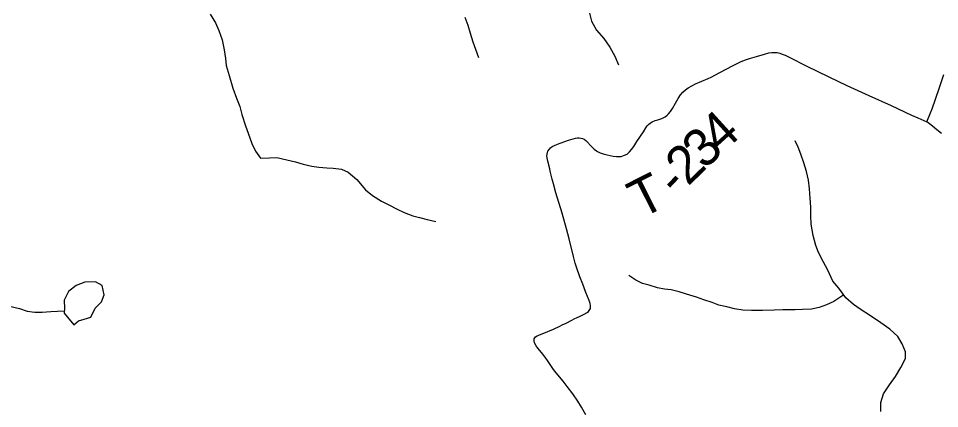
# Model space of a CAD drawing. Extents: x 0 to 34, y 0 to 22.
# Drawn here: x 5.89 to 7.268, y 16.898 to 17.482 of the extents above; entities that cross this region are included whole.
import ezdxf

# ---------------------------------------------------------------- set-up
doc = ezdxf.new("R2010")
doc.units = 0
for name, color, linetype in [('GM_X_Minor_Lake', 7, 'Continuous'), ('GM_X_Minor_River', 7, 'Continuous'), ('GM_X_Township_Road', 7, 'Continuous'), ('GM_X_Township_Road_Text', 7, 'Continuous')]:
    doc.layers.add(name, color=color, linetype=linetype)

msp = doc.modelspace()

# ---------------------------------------------------------------- linework, layer by layer
at = {"layer": 'GM_X_Minor_Lake'}
for points in [[(5.9725, 17.0228), (5.9798, 17.0291), (5.9882, 17.0317), (5.9981, 17.0346), (6.0044, 17.0478), (6.014, 17.0575), (6.0179, 17.0681), (6.0151, 17.0818), (6.0049, 17.0873), (5.989, 17.0871), (5.9764, 17.082), (5.9649, 17.073), (5.9583, 17.0598), (5.9585, 17.0477), (5.9584, 17.0404)], [(5.9584, 17.0404), (5.9725, 17.0228)]]:
    msp.add_lwpolyline(points, dxfattribs=at)
at = {"layer": 'GM_X_Minor_River'}
for points in [[(6.1768, 17.4886), (6.1846, 17.4756), (6.1897, 17.4637), (6.1949, 17.45), (6.1977, 17.4351), (6.1998, 17.4218), (6.2007, 17.4115), (6.2051, 17.3966), (6.2105, 17.3775), (6.216, 17.3627), (6.2211, 17.35), (6.2243, 17.3382), (6.2298, 17.321), (6.2334, 17.31), (6.2389, 17.2947), (6.2448, 17.2832), (6.2522, 17.2725), (6.2655, 17.2734), (6.2765, 17.2736), (6.2916, 17.2704), (6.3044, 17.2671), (6.3158, 17.2636), (6.329, 17.2607), (6.3392, 17.259), (6.3513, 17.2581), (6.3608, 17.2576), (6.3733, 17.2562), (6.3835, 17.2515), (6.3962, 17.2407), (6.4092, 17.2253), (6.4197, 17.2168), (6.4333, 17.2083), (6.4442, 17.2028), (6.4566, 17.1965), (6.4671, 17.1914), (6.4799, 17.1863), (6.4902, 17.1839), (6.5015, 17.1807), (6.5147, 17.1778)], [(6.5578, 17.4841), (6.5622, 17.4719), (6.5658, 17.4601), (6.5698, 17.4471), (6.5738, 17.436), (6.5786, 17.4234)], [(6.7445, 17.4897), (6.7477, 17.4779), (6.7551, 17.4645), (6.7659, 17.4518), (6.7748, 17.4391), (6.7826, 17.4253), (6.7881, 17.4123)], [(7.2026, 16.9457), (7.2107, 16.9589), (7.2177, 16.9725), (7.2175, 16.9823), (7.2127, 16.9946), (7.2061, 17.0053), (7.1941, 17.0165), (7.1806, 17.0262), (7.1652, 17.0363), (7.1494, 17.0464), (7.1397, 17.0534), (7.1284, 17.0634), (7.1177, 17.078), (7.1087, 17.0884), (7.101, 17.1049), (7.0943, 17.1179), (7.0873, 17.1313), (7.0833, 17.1416), (7.0794, 17.1569), (7.0762, 17.174), (7.076, 17.1869), (7.0758, 17.1995), (7.0749, 17.2128), (7.0739, 17.2268), (7.0722, 17.2398), (7.0694, 17.2527), (7.0654, 17.2657), (7.0607, 17.2787), (7.0566, 17.289), (7.0522, 17.2986)], [(7.125, 17.0681), (7.1102, 17.058), (7.0991, 17.0529), (7.0884, 17.0492), (7.0766, 17.0467), (7.0633, 17.0458), (7.0523, 17.0456), (7.0338, 17.0455), (7.0209, 17.0449), (7.0034, 17.0444), (6.9871, 17.0443), (6.9738, 17.0448), (6.9614, 17.0469), (6.95, 17.0498), (6.9379, 17.0522), (6.9281, 17.0562), (6.9157, 17.0605), (6.9047, 17.0645), (6.8896, 17.0689), (6.8787, 17.0725), (6.8666, 17.0753), (6.8568, 17.0766), (6.8462, 17.0783), (6.8337, 17.0823), (6.8239, 17.0851), (6.8141, 17.0898), (6.8036, 17.0968)], [(5.8762, 17.0508), (5.8914, 17.0475), (5.9027, 17.0435), (5.9144, 17.0422), (5.9254, 17.0421), (5.9383, 17.043), (5.9584, 17.0439)], [(7.1806, 16.8929), (7.1808, 16.9065), (7.1847, 16.9194), (7.1937, 16.9333), (7.2026, 16.9457)]]:
    msp.add_lwpolyline(points, dxfattribs=at)
at = {"layer": 'GM_X_Township_Road'}
for points in [[(6.6822, 17.2834), (6.6844, 17.2864), (6.6862, 17.2881), (6.6887, 17.2899), (6.692, 17.2917), (6.6965, 17.2937), (6.7129, 17.2994), (6.7237, 17.3025), (6.7267, 17.3029), (6.7292, 17.303), (6.7317, 17.3027), (6.734, 17.302), (6.7363, 17.3009), (6.7389, 17.2992), (6.7412, 17.2972), (6.7467, 17.2913), (6.7515, 17.2864), (6.7549, 17.2837), (6.7565, 17.2827), (6.7603, 17.2807), (6.765, 17.2791), (6.771, 17.2775), (6.7801, 17.2756), (6.7851, 17.275), (6.79, 17.2752), (6.7918, 17.2754), (6.7971, 17.277), (6.801, 17.2789), (6.8046, 17.2823), (6.8074, 17.2857), (6.8107, 17.2902), (6.8155, 17.2974), (6.8251, 17.3119), (6.8289, 17.3183), (6.8307, 17.3209), (6.8328, 17.3231), (6.8356, 17.3255), (6.8382, 17.3271), (6.8427, 17.3291), (6.8469, 17.3301), (6.8528, 17.3321), (6.8577, 17.3347), (6.8606, 17.337), (6.8628, 17.3391), (6.8657, 17.3424), (6.8689, 17.347), (6.8733, 17.3552), (6.8771, 17.3623), (6.8805, 17.3674), (6.8842, 17.3716), (6.8883, 17.3752), (6.8924, 17.378), (6.8977, 17.3812), (6.9033, 17.3839), (6.9124, 17.3878), (6.9221, 17.392), (6.9266, 17.3941), (6.9397, 17.401), (6.9594, 17.4115), (6.9716, 17.4175), (6.9779, 17.4201), (6.9838, 17.422), (6.9945, 17.4251), (7.0064, 17.4287), (7.013, 17.4304), (7.0173, 17.431), (7.0203, 17.4312), (7.0253, 17.4309), (7.0295, 17.4299), (7.033, 17.4287), (7.0376, 17.4268), (7.0454, 17.4229), (7.0686, 17.4111), (7.1027, 17.3944), (7.1297, 17.3817), (7.1624, 17.3667), (7.1958, 17.3516), (7.2267, 17.337), (7.2357, 17.3329), (7.245, 17.3293), (7.2492, 17.3269)], [(7.2492, 17.3269), (7.2548, 17.3405), (7.2574, 17.3468), (7.2678, 17.3768), (7.275, 17.3979)], [(7.2715, 17.3097), (7.2646, 17.315), (7.258, 17.3207), (7.2535, 17.3243), (7.2492, 17.3269)], [(6.739, 16.8883), (6.7326, 16.8996), (6.727, 16.9085), (6.7194, 16.9197), (6.7113, 16.9307), (6.7052, 16.9385), (6.6948, 16.9509), (6.6908, 16.9563), (6.6818, 16.9697), (6.6782, 16.9747), (6.6725, 16.9813), (6.6671, 16.9881), (6.6646, 16.9916), (6.6624, 16.9959), (6.6618, 16.9983), (6.6617, 17.0001), (6.6619, 17.0019), (6.6628, 17.0036), (6.6639, 17.005), (6.666, 17.0064), (6.6688, 17.0077), (6.682, 17.0131), (6.6906, 17.0166), (6.7001, 17.0211), (6.7035, 17.0228), (6.7097, 17.0257), (6.7179, 17.03), (6.7217, 17.0319), (6.7262, 17.034), (6.7295, 17.0356), (6.7367, 17.0391), (6.7409, 17.0416), (6.7429, 17.0431), (6.7442, 17.0444), (6.7452, 17.046), (6.7458, 17.0477), (6.7461, 17.0495), (6.746, 17.052), (6.7454, 17.0551), (6.744, 17.0592), (6.7391, 17.0712), (6.7343, 17.0838), (6.7302, 17.0948), (6.7251, 17.1093), (6.7232, 17.1152), (6.7204, 17.1254), (6.7139, 17.1518), (6.7103, 17.1668), (6.7038, 17.1901), (6.6942, 17.2209), (6.6904, 17.2341), (6.6885, 17.2413), (6.6857, 17.2533), (6.6849, 17.2569), (6.682, 17.2682), (6.681, 17.2731), (6.6808, 17.2762), (6.6809, 17.2786), (6.6814, 17.2811), (6.6822, 17.2834)]]:
    msp.add_lwpolyline(points, dxfattribs=at)

# ---------------------------------------------------------------- texts
at = {"layer": 'GM_X_Township_Road_Text'}
for s, rotation, p in [('4', 42.2502, (6.9418, 17.2783)), ('3', 44.2405, (6.9171, 17.2543)), ('2', 44.218, (6.892, 17.2299)), ('T', 26.82, (6.8214, 17.1814)), ('-', 46.7047, (6.8765, 17.2133))]:
    msp.add_text(s, height=0.0568, rotation=rotation, dxfattribs=at).set_placement(p)

doc.saveas('drawing.dxf')
